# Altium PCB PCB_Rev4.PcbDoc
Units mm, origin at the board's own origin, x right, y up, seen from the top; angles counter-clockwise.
Board outline 44.96 x 25.15 mm, 4 copper layers (Top Layer, Layer 1 (GND), Layer 2 (PWR), Bottom Layer), stack 1.716 mm thick; 62 components, 47 nets, 255 pads, 96 vias.
Unrouted connection lines stored in the file: 55.
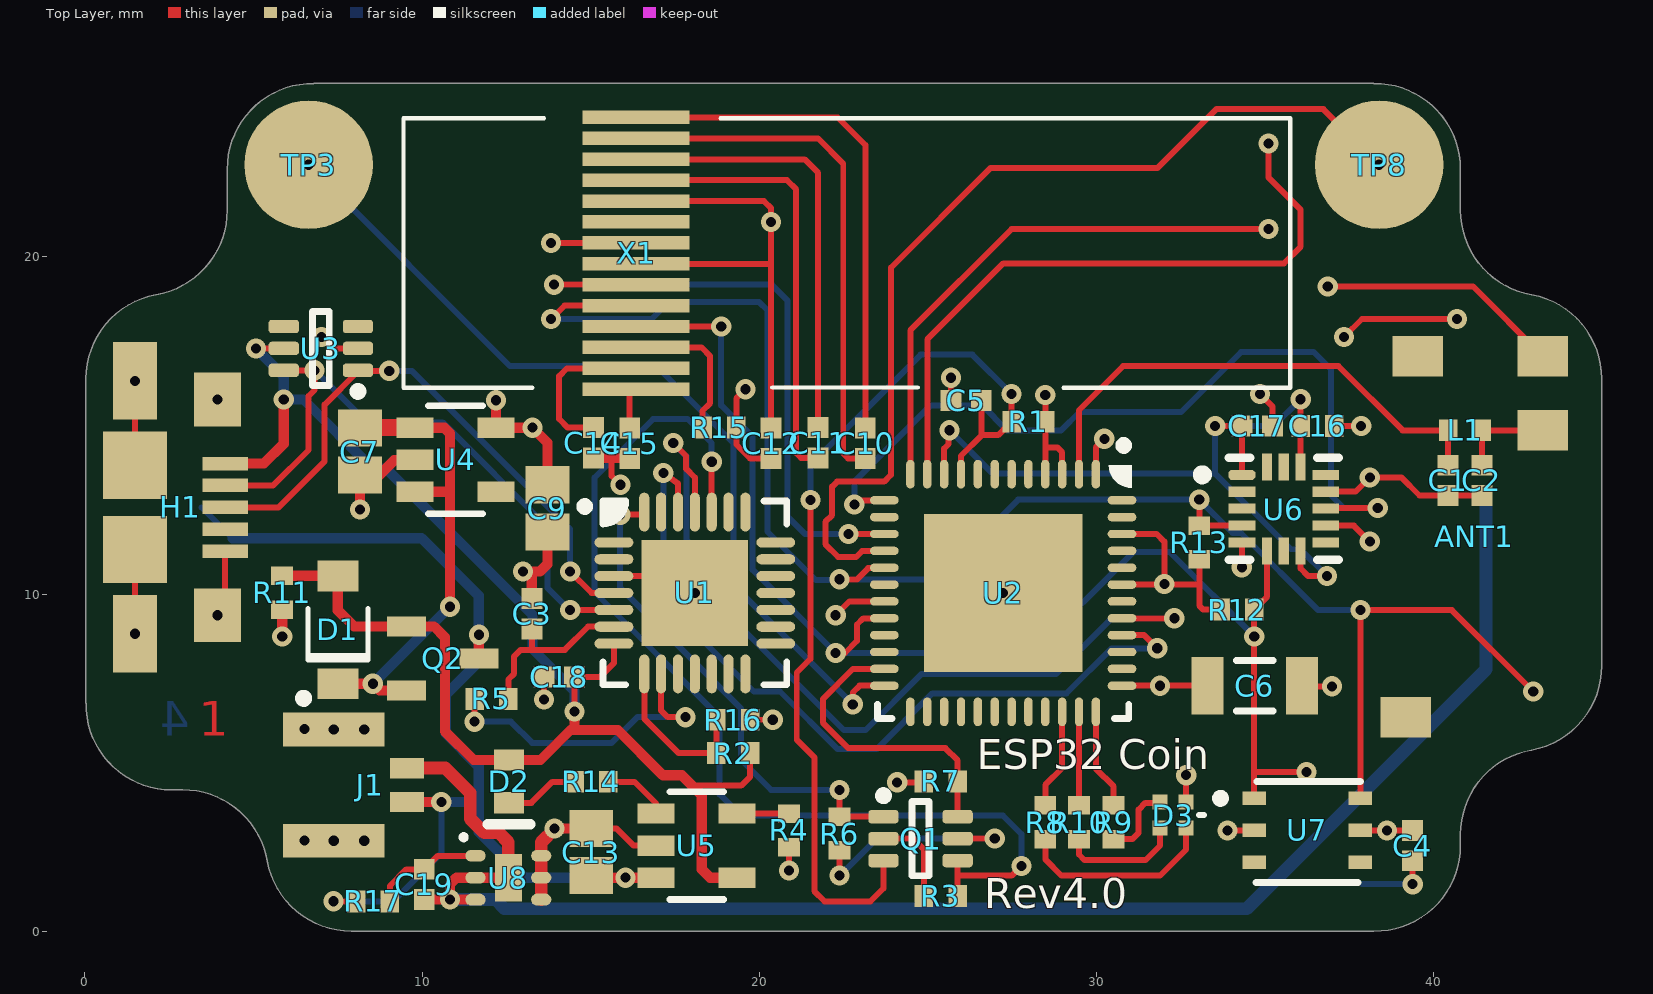
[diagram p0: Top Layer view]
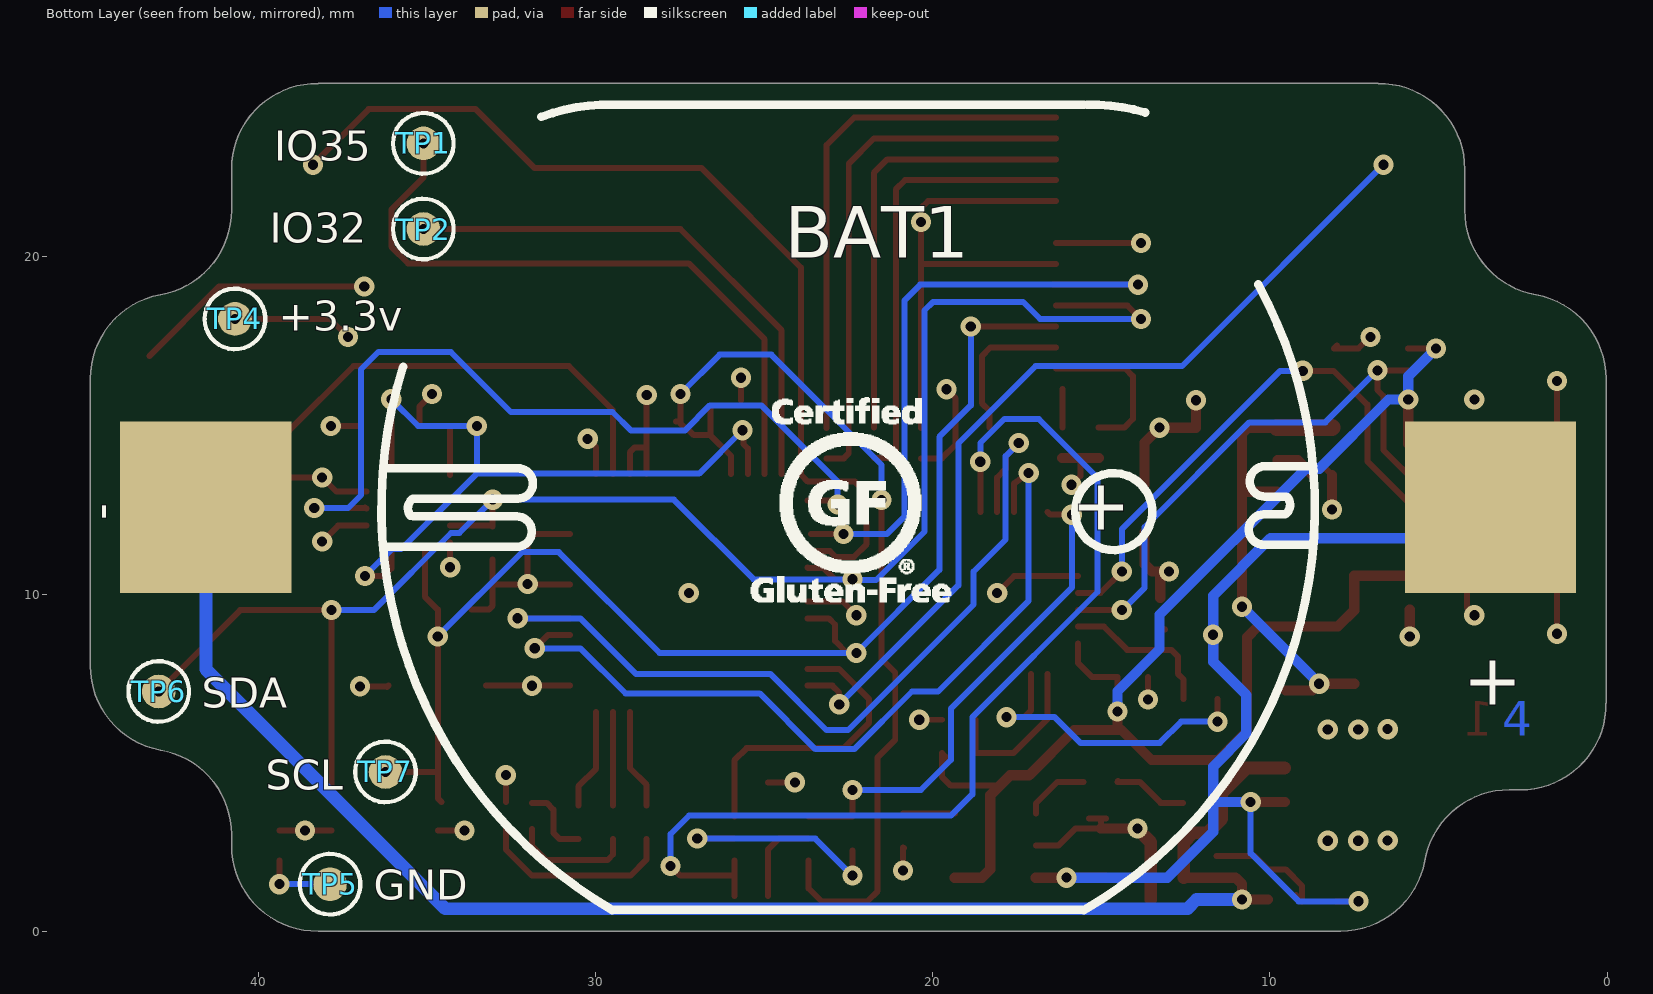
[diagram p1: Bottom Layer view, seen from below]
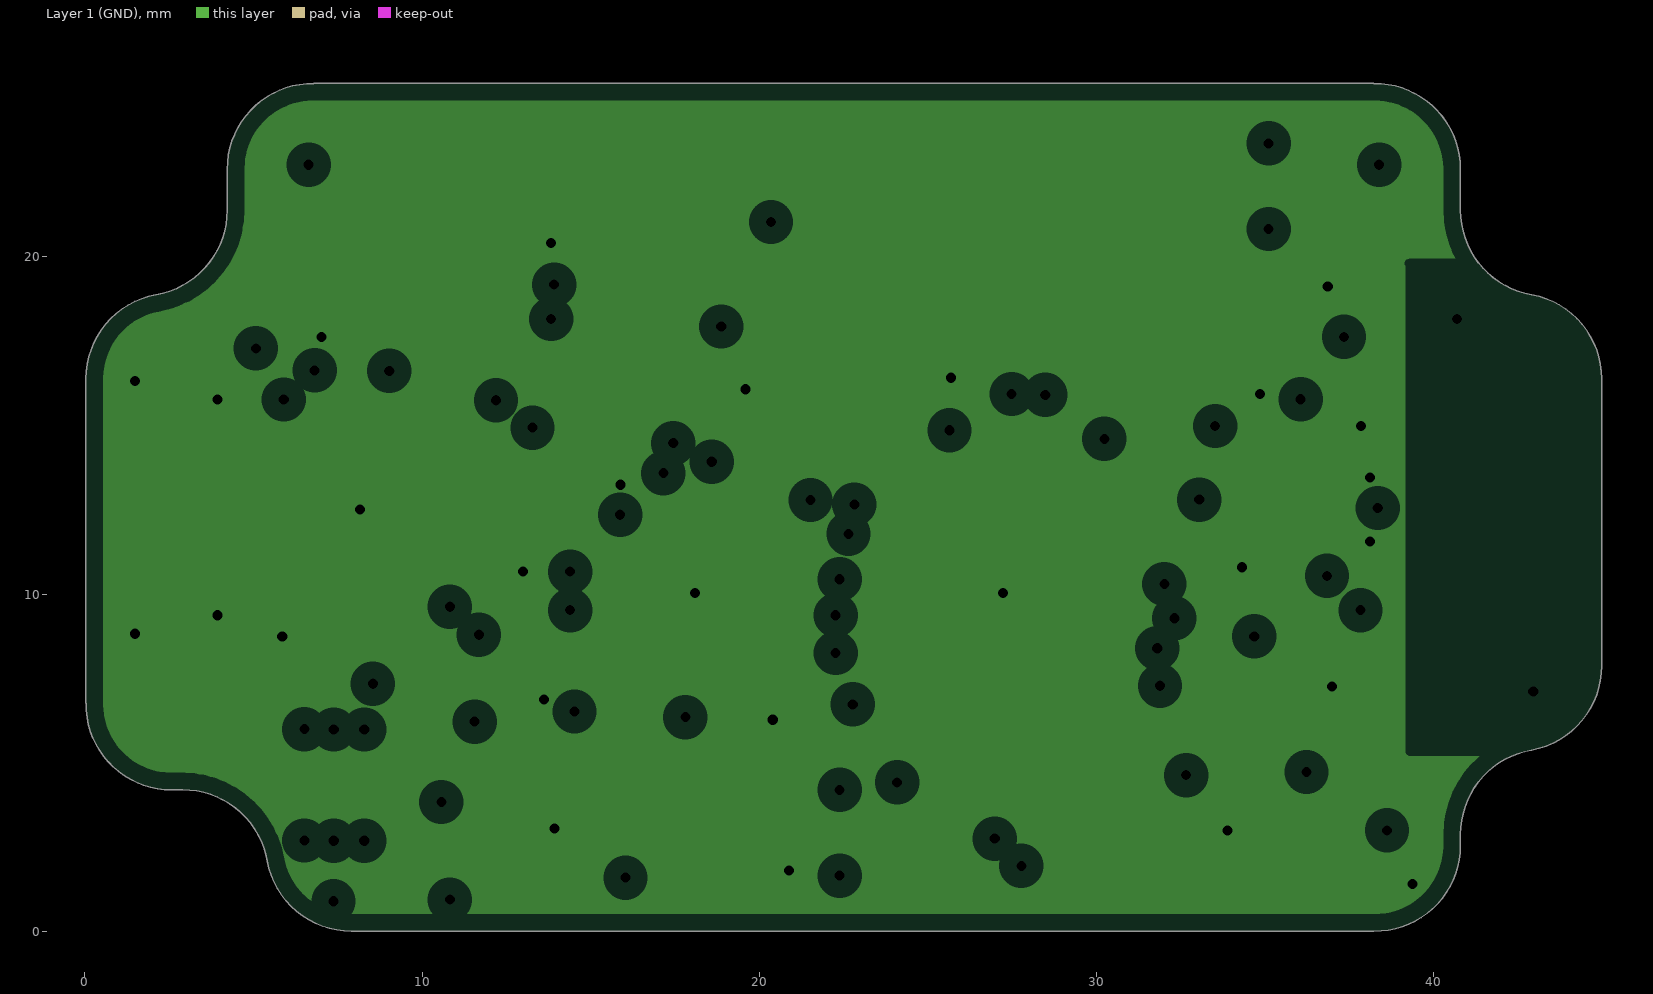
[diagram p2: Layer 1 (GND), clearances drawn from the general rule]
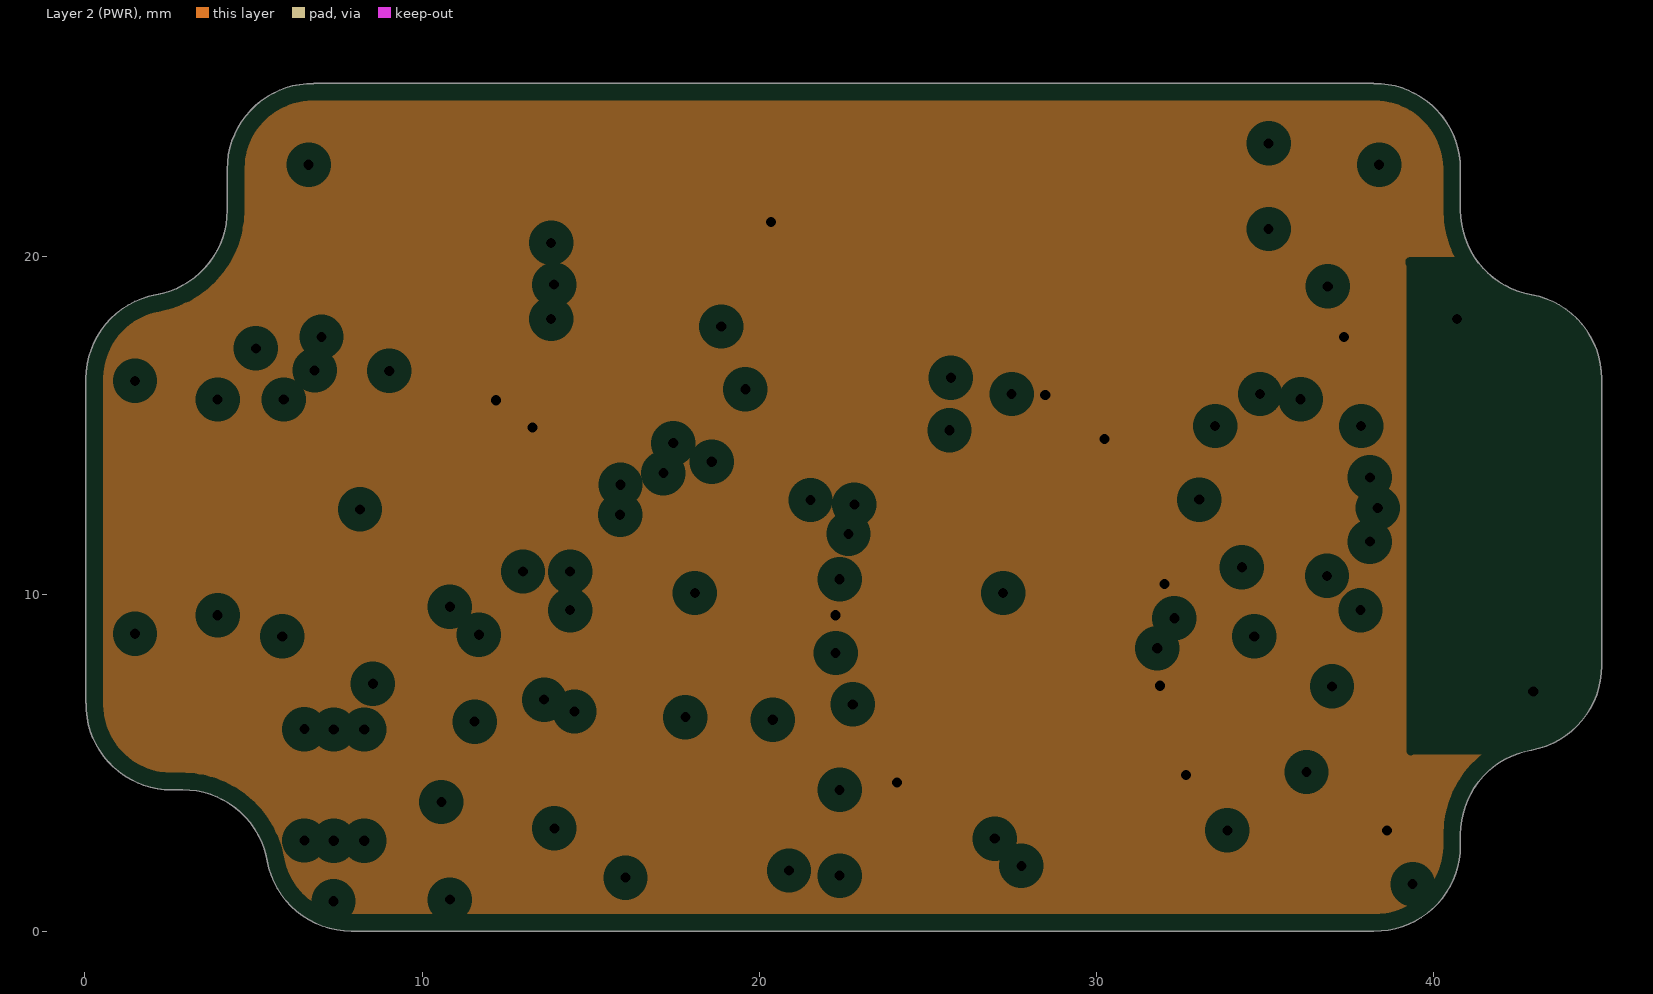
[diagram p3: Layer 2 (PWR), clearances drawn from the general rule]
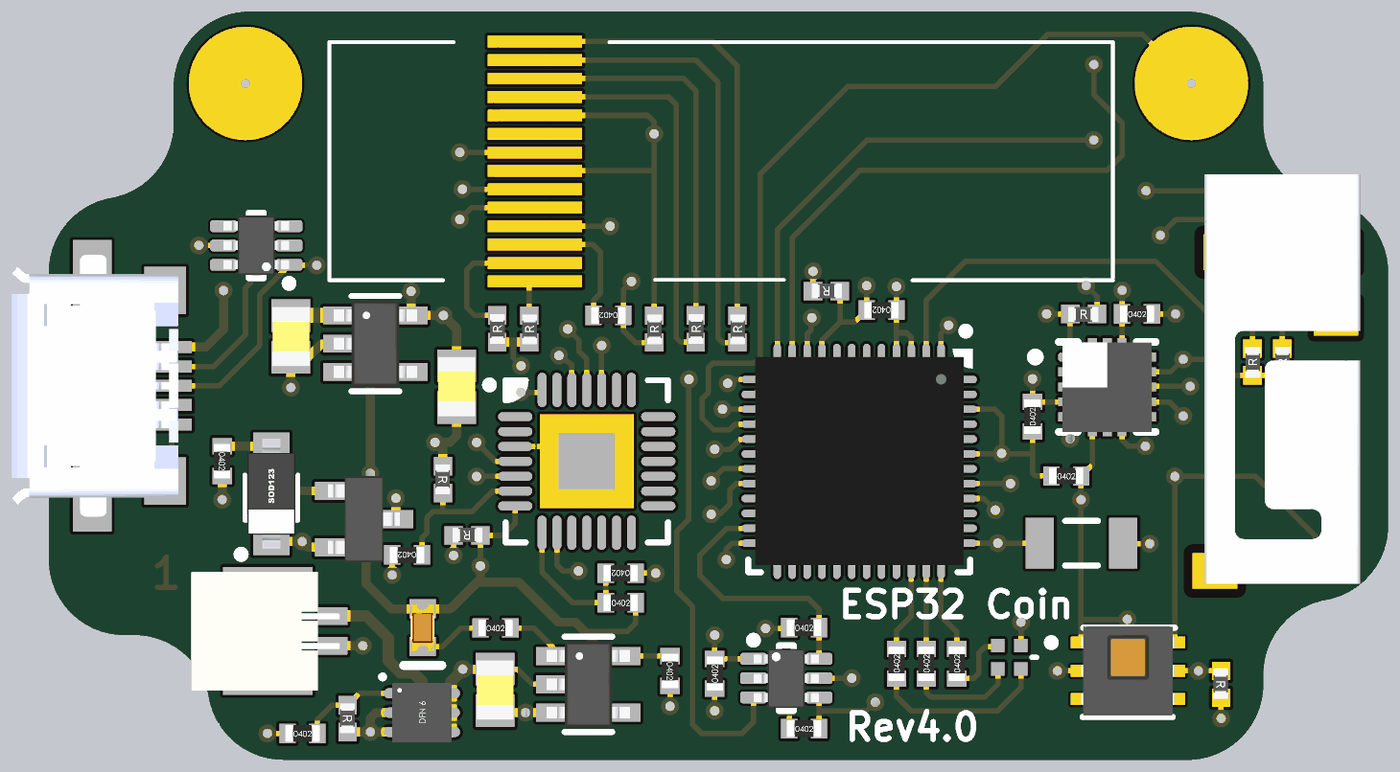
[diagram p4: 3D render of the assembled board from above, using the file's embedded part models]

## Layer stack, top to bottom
Top Solder: solder mask 0.0102, Solder Resist, Dk 3.5
Top Layer: signal copper 0.0356
Dielectric 2: prepreg 0.0711, PP-006, Dk 4.1
Layer 1 (GND): plane copper 0.035, net GND
Dielectric 1: dielectric 1.4326, FR-4, Dk 4.8
Layer 2 (PWR): plane copper 0.035, net +3.3V
Dielectric 3: prepreg 0.0711, PP-006, Dk 4.1
Bottom Layer: signal copper 0.0356
Bottom Solder: solder mask 0.0102, Solder Resist, Dk 3.5

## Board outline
2.572,4.196 cw(c2.572,6.736) 0.032,6.761 0.03,6.761 0.03,16.383 cw(c2.57,16.383) 2.111,18.881 ccw(c1.681,21.385) 4.221,21.385 4.221,22.604 cw(c6.761,22.604) 6.786,25.144 6.786,25.146 38.231,25.146 38.231,25.144 cw(c38.256,22.604) 40.796,22.604 40.796,21.385 ccw(c43.336,21.385) 42.907,18.881 cw(c42.448,16.383) 44.988,16.383 44.988,7.874 cw(c42.448,7.874) 42.907,5.376 ccw(c43.336,2.872) 40.796,2.872 40.796,2.542 cw(c38.256,2.542) 38.231,0.002 38.231,0 7.903,0 7.903,0.005 cw(c7.903,2.545) 5.405,2.086 ccw(c2.902,1.656) 2.902,4.196

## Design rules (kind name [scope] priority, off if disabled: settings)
Clearance Clearance_H1 [All vs InComponent('H1')] p1: gap=0.241 ignorepadtopadclearanceinfootprint=FALSE
Clearance Clearance_U3 [All vs InComponent('U3')] p2: gap=0.241 ignorepadtopadclearanceinfootprint=FALSE
Clearance Clearance_Q1 [All vs InComponent('Q1')] p3: gap=0.241 ignorepadtopadclearanceinfootprint=FALSE
Clearance Clearance_X1 [All vs InComponent('X1')] p4: gap=0.216 ignorepadtopadclearanceinfootprint=FALSE
Clearance Clearance_U2 [All vs InComponent('U2')] p5: gap=0.241 ignorepadtopadclearanceinfootprint=FALSE
Clearance Clearance_U1 [All vs InComponent('U1')] p6: gap=0.198 ignorepadtopadclearanceinfootprint=FALSE
Clearance Clearance_U6 [All vs InComponent('U6')] p7: gap=0.191 ignorepadtopadclearanceinfootprint=FALSE
Clearance [All] p8: gap=0.254 ignorepadtopadclearanceinfootprint=FALSE except(0: Arc-Hole Track-Hole SMDPad-Hole THPad-Hole Via-Hole Fill-Hole Poly-Hole Region-Hole Text-Hole)
MinimumSolderMaskSliver MinimumSolderMaskSliver_X1 [All vs InComponent('X1')] p1: minsoldermaskwidth=0.015
MinimumSolderMaskSliver [All] p2: minsoldermaskwidth=0.025
PlaneClearance [All] p1: clearance=0.508
PlaneConnect [All] p1: planeconnectstyle=Direct reliefexpansion=0.508 reliefentries=4 reliefconductorwidth=0.254 reliefairgap=0.254
PolygonConnect [All] p1: connectstyle=Relief reliefconductorwidth=0.254 reliefentries=4 polygonreliefangle="90 Angle" airgapwidth=0.254
RoutingVias [All] p1: holewidth=0.3 width=0.6 viastyle="Through Hole" minholewidth=0.3 minwidth=0.6 maxholewidth=0.3 maxwidth=0.6
SilkToSilkClearance [All] p1: silktosilkclearance=0.127
SilkToSolderMaskClearance [IsPad] p1: minsilkscreentomaskgap=0.127 clearancetoexposedcopper=TRUE
SolderMaskExpansion [All] p1: expansion=0.102
Width [All] p1: maxlimit=1.016 minlimit=0.178 preferedwidth=0.178
25 further rules are at their usual default settings.

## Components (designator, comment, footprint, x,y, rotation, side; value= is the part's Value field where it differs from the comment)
ANT1 "RF ANT 2.4GHZ STAMPED MET SLD" PRO-OB-440 43.235,17.059 r0 top locked
BAT1 "BATTERY-HOLDER (2450)" BU2450SM-JJ-GTR 22.509,12.573 r0 bottom locked value="Coin Cell Holder"
C1 "=Value" CAPC1005X56N#1 40.432,13.373 r90 top
C2 "=Value" CAPC1005X56N#1 41.432,13.373 r90 top
C3 "4.7uF" CAPC1005X56N#2 13.263,9.42 r270 top
C4 "0.1uF" CAPC1005X56N#1 39.379,2.542 r270 top
C5 "0.1uF" CAPC1005X56N#2 26.133,15.748 r180 top
C6 "100uF" CAPC3216X160L 34.695,7.283 r0 top
C7 "10uF" CAPC2012X140N 8.158,14.228 r270 top
C9 "10uF" CAPC2012X140N 13.716,12.543 r270 top
C10 "1uF" CAPC1005X56N#2 23.144,14.478 r90 top
C11 "1uF" CAPC1005X56N#2 21.747,14.489 r90 top
C12 "1uF" CAPC1005X56N#2 20.35,14.478 r90 top
C13 "10uF" CAPC2012X140N 15.016,2.351 r90 top
C14 "4.7uF" CAPC1005X56N#2 15.079,14.489 r90 top
C15 "2.2uF" CAPC1005X56N#2 16.159,14.478 r90 top
C16 "0.1uF" RESC1005X40L 36.557,14.986 r0 top
C17 "0.1uF" CAPC1005X56N#2 34.767,14.986 r0 top
C18 "1uF" CAPC1005X56N#2 14.069,7.544 r180 top
C19 "0.1uF" CAPC1005X56N#2 10.063,1.39 r270 top
D1 "MBR0520-TP" SOD123 7.502,8.941 r90 top value=MBR0520
D2 "LED_0603" LED1608X55N-RED 12.582,4.445 r90 top value=Red
D3 "RGB" FC-B1010RGBT-HG 32.273,3.449 r0 top value="RGB Led"
H1 "Micro USB" 1981584-1 2.824,12.573 r270 top locked
J1 "CON2" JST_Micro_2PIN 9.555,4.336 r270 top locked
L1 "Inductor" RESC1005X40L 40.932,14.859 r180 top value=1.8nH
Q1 "BC847S" SOT65P210X110-6N 24.784,2.723 r0 top value=2NPN
Q2 "FDN340P" SOT95P240X110-3N 10.609,8.09 r0 top locked value="Mosfet P-H"
R1 "10K" RESC1005X40L 27.983,15.113 r180 top
R2 "22.1K" RESC1005X40L 19.227,5.283 r0 top
R3 "10K" RESC1005X40L 25.384,1.051 r0 top
R4 "43K" RESC1005X40L 20.883,2.99 r270 top
R5 "4.7K" RESC1005X40L 12.057,6.89 r180 top
R6 "10K" RESC1005X40L 22.382,2.898 r90 top
R7 "10K" RESC1005X40L 25.384,4.445 r0 top
R8 "1K" RESC1005X40L 28.483,3.233 r90 top
R9 "1K" RESC1005X40L 30.51,3.233 r90 top
R10 "1K" RESC1005X40L 29.483,3.233 r90 top
R11 "100K" RESC1005X40L 5.851,10.041 r270 top
R12 "4.7K" RESC1005X40L 34.18,9.541 r0 top
R13 "4.7K" RESC1005X40L 33.05,11.533 r90 top
R14 "2K" RESC1005X40L 15.024,4.434 r0 top
R15 "390K" RESC1005X40L 18.818,14.939 r180 top
R16 "47.5K" RESC1005X40L 19.227,6.274 r180 top
R17 "100R" RESC1005X40L 8.547,0.889 r0 top
TP1 "Test Point, 1mm Top Layer" TP100TL#1 35.107,23.368 r90 bottom
TP2 "Test Point, 1mm Top Layer" TP100TL#1 35.107,20.828 r90 bottom
TP3 "Test Point, 1mm Top Layer" TP100TL#2 11.485,24.765 r90 top
TP4 "Test Point, 1mm Top Layer" TP100TL#1 40.695,18.161 r90 bottom
TP5 "Test Point, 1mm Top Layer" TP100TL#1 37.876,1.397 r90 bottom
TP6 "Test Point, 1mm Top Layer" TP100TL#1 42.956,7.112 r90 bottom
TP7 "Test Point, 1mm Top Layer" TP100TL#1 36.231,4.725 r90 bottom
TP8 "Test Point, 1mm Top Layer" TP100TL#3 38.384,22.733 r90 top
U1 "CP2102N" 28-QFN 18.089,10.033 r0 top locked
U2 "ESP32-PICO-D4" QFN48 27.233,10.033 r270 top
U3 "PESD5V0L5UY" SOT65P210X110-6N 6.997,17.312 r180 top value=ESD
U4 "HT7833" SOT95P280X144-5N 10.992,13.986 r0 top value="LDO 3.3V"
U5 "SL4054ST25P" SOT95P280X144-5N 18.143,2.54 r0 top
U6 "ACCEL" QFN3X3_16_1.2 35.556,12.522 r0 top value=LIS3DHTR
U7 "HDC1080DMBT" HDC1080 36.255,2.992 r0 top value=Humidity/Temperature
U8 "XB6566H0" "DFN-6 2x2mm" 12.557,1.59 r0 top value="Battery Protection"
X1 "OLED_GLASS 96x16" "OLED_GLASS 96x16" 9.449,16.117 r180 top locked

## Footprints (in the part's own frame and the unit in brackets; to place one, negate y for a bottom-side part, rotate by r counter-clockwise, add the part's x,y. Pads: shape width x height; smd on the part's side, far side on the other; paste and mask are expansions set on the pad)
28-QFN [mm] "QFN, 28-Leads, Body 5.00x5.00mm, Pitch 0.50mm, Thermal Pad 3.15x3.15mm, IPC Medium Density"
  oval 1.15x0.3 smd: 1(-2.4,1.5) 2(-2.4,1) 3(-2.4,0.5) 4(-2.4,0) 5(-2.4,-0.5) 6(-2.4,-1) 7(-2.4,-1.5) 15(2.4,-1.5) 16(2.4,-1) 17(2.4,-0.5) 18(2.4,0) 19(2.4,0.5) 20(2.4,1) 21(2.4,1.5)
  oval 0.3x1.15 smd: 8(-1.5,-2.4) 9(-1,-2.4) 10(-0.5,-2.4) 11(0,-2.4) 12(0.5,-2.4) 13(1,-2.4) 14(1.5,-2.4) 22(1.5,2.4) 23(1,2.4) 24(0.5,2.4) 25(0,2.4) 26(-0.5,2.4) 27(-1,2.4) 28(-1.5,2.4)
  rect 3.15x3.15 smd paste-0.635: 29(0,0)
  silkscreen extent -3.39,-2.73 2.73,2.73, body extent -2.58,-2.57 2.57,2.58, height 1
1981584-1 [mm] "CONN RCPT MICRO USB TYPE AB"
  rect 0.4x1.35 smd: 1(-1.3,1.338) 2(-0.65,1.338) 3(0,1.338) 4(0.65,1.338) 5(1.3,1.338)
  rect 2.3x1.3 smd: 6(-3.75,-1.337) 6(3.75,-1.337)
  rect 1.6x1.4 smd: 6(-3.2,1.113) 6(3.2,1.113)
  rect 2x1.9 smd: 6(-1.25,-1.337) 6(1.25,-1.337)
  body extent -4.4,-4.05 4.4,1.55, height 2.75
BU2450SM-JJ-GTR [mm] "HOLDER,BATT,COIN,24.5MM,SMT"
  rect 5.08x5.08 smd: 1(-19.05,0) 2(19.05,0)
  silkscreen extent -13.84,-11.94 13.84,11.95, body extent -21.38,-14.48 88.52,12.32, height 7.38
CAPC1005X56N#1 [mm] "Chip Capacitor, 2-Leads, Body 1.0x0.5mm, IPC Medium Density (0402 ceramic)"
  rect 0.62x0.62 smd paste-0.305: 1(-0.45,0) 2(0.45,0)
  body extent -0.55,-0.3 0.55,0.3, height 0.6
CAPC1005X56N#2 [mm] "Chip Capacitor, 2-Leads, Body 1.0x0.5mm, IPC Medium Density (0402 ceramic)"
  rect 0.62x0.62 smd: 1(-0.45,0) 2(0.45,0)
  body extent -0.55,-0.3 0.55,0.3, height 0.6
CAPC2012X140N [mm] "Chip Capacitor, 2-Leads, Body 2.0x1.3mm, IPC Medium Density (0805 ceramic)"
  rect 1.1x1.3 smd: 1(-0.7,0) 2(0.7,0)
  body extent -1,-0.62 1,0.63, height 1.24
CAPC3216X160L [mm] "Chip Capacitor, 2-Leads, Body 3.2x1.6mm, IPC Least Density(C1206)"
  rect 0.95x1.7 smd: 1(-1.4,0) 2(1.4,0)
  silkscreen extent -0.55,-0.75 0.55,0.75, body extent -1.7,-0.9 1.7,0.9, height 1.9
"DFN-6 2x2mm" [mm] "DFN, 6-Leads, Body 2.00x2.00mm, Pitch 0.65mm, IPC High Density"
  oval 0.6x0.35 smd: 1(-0.975,0.65) 2(-0.975,0) 3(-0.975,-0.65) 4(0.975,-0.65) 5(0.975,0) 6(0.975,0.65)
  rect 0.8x1.4 smd paste-0.15: 7(0,0)
  silkscreen extent -1.37,1.15 -1.27,1.25, body extent -1,-1 2.65,1, height 4.99
FC-B1010RGBT-HG [mm] "LED,RGB,SMD,RoHS"
  rect 0.45x0.45 smd: 1(0.387,0.388) 2(0.387,-0.387) 3(-0.387,-0.387) 4(-0.387,0.388)
  silkscreen extent 0.76,0 0.91,0, body extent -0.53,-0.55 0.53,0.58, height 1.2
HDC1080 [mm] "Temp/Humidity Sensor"
  rect 0.7x0.4 smd paste-0.381 mask+0.076: 1(-1.575,0.95) 2(-1.575,0) 3(-1.575,-0.95) 4(1.575,-0.95) 5(1.575,0) 6(1.575,0.95)
  silkscreen extent -2.7,-1.55 1.57,1.45, body extent -1.55,-1.5 1.55,1.5, height 0.85
JST_Micro_2PIN [mm]
  rect 0.6x1 smd: 1(0.5,0) 2(-0.5,0)
  rect 1x3 smd: ""(-1.65,-2.175) ""(1.65,-2.175)
  body extent -1.99,-4.74 2,0.24, height 2.9
LED1608X55N-RED [mil] "Chip LED RED, 2-Leads, Body 1.6x0.8mm, IPC Medium Density (0603 med)"
  rect 25x35 smd: 1(-25,0) 2(25,0)
  silkscreen extent -50,-25 -50,25, body extent -31,-16 31,16, height 24
"OLED_GLASS 96x16" [mm] "OLED_GLASS 96x16"
  rect 3.175x0.4 smd paste-2.54: 1(-6.9,-8.02) 2(-6.9,-7.4) 3(-6.9,-6.78) 4(-6.9,-6.16) 5(-6.9,-5.54) 6(-6.9,-4.92) 7(-6.9,-4.3) 8(-6.9,-3.68) 9(-6.9,-3.06) 10(-6.9,-2.44) 11(-6.9,-1.82) 12(-6.9,-1.2) 13(-6.9,-0.58) 14(-6.9,0.04)
  silkscreen extent -26.3,-8 0,0, body extent -26.3,-8 0,0, height 2
PRO-OB-440 [mm] "RF ANT 2.4GHZ STAMPED MET SLD"
  rect 1.5x1.2 smd paste-0.762 mask+0.2: 1(0,0) 2(0,-2.2)
  rect 1.5x1.2 smd paste-0.762 mask+0.3: 3(-3.7,0) 4(-4.064,-10.709)
  body extent -4.42,-11.14 7.98,2.61, height 3.56
QFN3X3_16_1.2 [mm] "QFN3X3_16_1.2"
  oct 0.8x0.3 smd: 1(-1.245,1.016)
  rect 0.8x0.3 smd: 2(-1.245,0.514) 3(-1.245,0.013) 4(-1.245,-0.489) 5(-1.245,-0.991) 9(1.245,-0.991) 10(1.245,-0.489) 11(1.245,0.013) 12(1.245,0.514) 13(1.245,1.016)
  rect 0.3x0.8 smd: 6(-0.495,-1.245) 7(0,-1.245) 8(0.495,-1.245) 14(0.495,1.245) 15(0,1.245) 16(-0.495,1.245)
  silkscreen extent -2.54,-1.5 1.63,1.52, body extent -1.51,-1.5 1.51,1.5, height 0.81
QFN48 [mm] "QFN, 48-Leads, Body 7x7mm, Pitch 0.5mm, IPC Medium Density"
  oval 0.85x0.25 smd: 1(-3.525,2.75) 2(-3.525,2.25) 3(-3.525,1.75) 4(-3.525,1.25) 5(-3.525,0.75) 6(-3.525,0.25) 7(-3.525,-0.25) 8(-3.525,-0.75) 9(-3.525,-1.25) 10(-3.525,-1.75) 11(-3.525,-2.25) 12(-3.525,-2.75) 25(3.525,-2.75) 26(3.525,-2.25) 27(3.525,-1.75) 28(3.525,-1.25) 29(3.525,-0.75) 30(3.525,-0.25) 31(3.525,0.25) 32(3.525,0.75) 33(3.525,1.25) 34(3.525,1.75) 35(3.525,2.25) 36(3.525,2.75)
  oval 0.25x0.85 smd: 13(-2.75,-3.525) 14(-2.25,-3.525) 15(-1.75,-3.525) 16(-1.25,-3.525) 17(-0.75,-3.525) 18(-0.25,-3.525) 19(0.25,-3.525) 20(0.75,-3.525) 21(1.25,-3.525) 22(1.75,-3.525) 23(2.25,-3.525) 24(2.75,-3.525) 37(2.75,3.525) 38(2.25,3.525) 39(1.75,3.525) 40(1.25,3.525) 41(0.75,3.525) 42(0.25,3.525) 43(-0.25,3.525) 44(-0.75,3.525) 45(-1.25,3.525) 46(-1.75,3.525) 47(-2.25,3.525) 48(-2.75,3.525)
  rect 4.7x4.7 smd paste-0.5: 49(0,0)
  silkscreen extent -4.5,-3.72 3.72,3.81, body extent -3.52,-3.51 3.5,3.51, height 0.78
RESC1005X40L [mm] "Chip Resistor, 2-Leads, Body 1.0x0.5mm, IPC Medium Density (0402)"
  rect 0.55x0.65 smd: 1(-0.5,0) 2(0.5,0)
  body extent -0.57,-0.27 0.58,0.28, height 0.41
SOD123 [mil] "Molded Diode, 2-Leads, Body 2.85x1.8mm, IPC Medium Density (SOD123)"
  rect 36x48 smd: 1(-63,0) 2(63,0)
  silkscreen extent -85,-35 25,45, body extent -73,-31 73,31, height 50
SOT65P210X110-6N [mm] "SC70, 6-Leads, Body 2.4x2.2mm (max), Pitch 0.65mm, IPC Medium Density"
  rrect50% 0.9x0.4 smd mask+0.076: 1(-1.1,0.675) 2(-1.1,0.025) 3(-1.1,-0.625) 4(1.1,-0.625) 5(1.1,0.025) 6(1.1,0.675)
  silkscreen extent -1.22,-1.07 0.25,1.42, body extent -1.1,-0.97 1.1,1.01, height 0.99
SOT95P240X110-3N [mm] "SOT23, 3-Leads, Body 3.0x2.5mm (max), Pitch 0.95mm, IPC Medium Density"
  rect 1.15x0.6 smd: 1(-1.075,0.95) 2(-1.075,-0.95) 3(1.075,0)
  body extent -1.2,-1.45 1.2,1.45, height 0.99
SOT95P280X144-5N [mm] "SOT23, 5-Leads, Body 3.1x3.0mm (max), Pitch 0.95mm, IPC Medium Density (RFMD SOT23-5)"
  rect 1.1x0.6 smd: 1(-1.2,0.95) 2(-1.2,0) 3(-1.2,-0.95) 4(1.2,-0.95) 5(1.2,0.95)
  silkscreen extent -0.8,-1.6 0.8,1.6, body extent -1.4,-1.45 1.4,1.45, height 1.45
TP100TL#1 [mm] "Test Point"
  round 1 smd paste-0.5 mask+0.076: 1(0,0)
  silkscreen extent -0.9,-0.9 0.9,0.9
TP100TL#2 [mm] "Test Point"
  round 3.81 smd paste-2.032 mask+0.076: 1(-2.032,4.851)
TP100TL#3 [mm] "Test Point"
  round 3.81 smd paste-2.032 mask+0.076: 1(0,0)

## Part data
ANT1: library part PRO-OB-440, Manufacturer="Proant AB"
BAT1: library part BU2450SM-JJ-GTR, "HOLDER,BATT,COIN,24.5MM,SMT", Manufacturer=MPD
C1 C2: library part CAP_0402, "DNP"
C3 C14: library part CAP_0603, "CAP CER 4.7uF 16V 0402", Manufacturer=Kyocera, PartNumber=CM05X5R475M16AH
C4 C5 C16 C17 C19: library part CAP_0402, "CAP CER 0.1uF 16V 0402", Manufacturer=CCTC, PartNumber=TCC0402X5R104M160AT
C6: library part CAP_1206, "CAP CER 100uF 6.3V 1206", Manufacturer="Taiyo Yuden", PartNumber=JMK316BJ107ML-T
C7 C9: library part CAP_0805, "CAP 10uF 0805", Manufacturer=Murata, PartNumber=GRM21BB31C106KE15L
C10 C11 C12 C18: library part CAP_0603, "CAP CER 1uF 16V 0402", Manufacturer=Murata, PartNumber=GRM155R61C105KA12D
C13: library part CAP_0805, "CAP CER 10uF 16V 0805", Manufacturer=Samsung, PartNumber=CL21A106KOQNNNG
C15: library part CAP_0402, "CAP CER 2.2uF 16V 0402", Manufacturer=Samsung, PartNumber=CL05A225KO5NQNC
D1: "DIODE SCHOTTKY 20V 500MA SOD123", Manufacturer=CJ, PartNumber=MBR0520
D2: "LED RED CLEAR 0603 SMD", Manufacturer=FNO, PartNumber=FC-DA1608HRK-620D
D3: library part FC-B1010RGBT-HG, "LED,RGB LED,SMD,RoHS", Manufacturer=Foshan
H1: library part 1981584-1, "CONN RCPT MICRO USB TYPE AB", Manufacturer="REG CON", PartNumber=C21377
J1: library part JST_Micro_CONN_2PIN, "JST MIcro CONN 2POS"
L1: "Inductor 1.8nH 0402", Manufacturer=GFBE, PartNumber=BKW0603UC1N8KGT
Q1: "TRANS 2NPN 44V 0.1A SC-70-6", Manufacturer=Changjiang
Q2: "MOSFET P-CH 20V 2A SOT-23", Manufacturer="On Semi"
R1 R3 R6 R7: library part RES_0402, "RES SMD 10K OHM 0402", Manufacturer=Guangdong, PartNumber=RC-02W1002FT
R2: library part RES_0603, "RES SMD 22.1K OHM 0402", Manufacturer=Yageo, PartNumber=RC0402FR-0722K1L
R4: library part RES_0603, "RES SMD 43K OHM 0402", Manufacturer=Uniroyal, PartNumber=0402WGF4302TCE
R5 R12 R13: library part RES_0603, "RES SMD 4.7K OHM 0402", Manufacturer=Yageo, PartNumber=RC0402FR-074K7L
R8 R9 R10: library part RES_0402, "RES SMD 1K OHM 0402", Manufacturer=Yageo, PartNumber=RC0402FR-071KL
R11: library part RES_0603, "RES SMD 100K OHM 0402", Manufacturer="Uniroyal Elec", PartNumber=0402WGF1003TCE
R14: library part RES_0603, "RES SMD 2K OHM 1% 1/10W 0402", Manufacturer="LIZ Elec", PartNumber=CR0402FF2001G
R15: library part RES_0603, "RES SMD 390K OHM 0402", Manufacturer=Guangdong, PartNumber=RC-02W3903FT
R16: library part RES_0603, "RES SMD 47.5K OHM 0402", Manufacturer=Yageo, PartNumber=RC0402FR-0747K5L
R17: library part RES_0603, "RES SMD 100R OHM 1% 1/10W 0402", Manufacturer=Yageo, PartNumber=RC0402FR-07100RL
TP1 TP2 TP3 TP4 TP5 TP6 TP7 TP8: Manufacturer=N/A
U1: "IC BRIDGE USB TO UART 28QFN", Manufacturer="Silicon Labs", PartNumber=CP2102N-A01-GQFN28
U2: "RF Transceiver ICs QFN-48_7x7x05P RoHS", Manufacturer=Espressif
U3: "TVS SOT-363 RoHS", Manufacturer=Yenji
U4: "IC LDO 3.3V 0.5A SOT23-5", Manufacturer=Holtek
U5: "Charger IC Lithium-Ion/Polymer SOT23-5", Manufacturer=Techfuse
U6: library part E-05-177, "IC ACCEL 2-16G I2C/SPI 16LGA", Manufacturer=STMicro, PartNumber=LIS3DHTR
U7: "Humidity/Temperature Sensor", Manufacturer="Texas Instruments"
U8: "IC Battery Protection", Manufacturer=XySemi
X1: "96x16 OLED_GLASS", Manufacturer=N/A, PartNumber=ER-OLED0.69-1W

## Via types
v1: diameter 0.6, hole 0.3, Top Layer to Bottom Layer, tented both sides, 96 vias

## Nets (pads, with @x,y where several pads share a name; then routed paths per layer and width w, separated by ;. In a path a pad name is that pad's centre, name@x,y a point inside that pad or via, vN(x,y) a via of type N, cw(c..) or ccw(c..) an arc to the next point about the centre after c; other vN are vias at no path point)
+3.3V: C4.1 C6.1 C9.1 C12.2 D3.1 R1.1 R7.1 R12.1 R13.1 TP4.1 U2.1 U2.3 U2.4 U2.19 U2.37 U2.43 U2.46 U4.5 U7.5 X1.5 X1.8 | length 40.9
  Top Layer w0.178: X1.8 20.307,19.797 20.35,19.754 ; X1.5 20.141,21.657 20.35,21.448 v1(20.35,21.037) C12.2 ; v1(22.265,9.373) 22.675,9.783 U2.19 ; v1(24.09,4.417) R7.1@24.885,4.417 ; U2.4 28.483,14.351 ; v1(28.483,15.908) R1.1 28.483,14.351 ; U2.3 28.983,14.206 28.838,14.351 28.483,14.351 ; U2.1 29.983,14.353 v1(30.235,14.605) ; U2.37 C6.1@33.245,7.283 ; U2.43 33.05,10.283 ; U2.46 31.787,11.783 32.013,11.557 v1(32.013,10.3) ; D3.1 v1(32.661,4.631) ; R13.1 33.05,9.657 33.165,9.541 R12.1 ; v1(37.342,17.628) 37.876,18.161 v1(40.695,18.161) ; U7.5 v1(38.617,2.992) C4.1
  Top Layer w0.305: v1(12.192,15.748) U4.5 v1(13.276,14.936) 13.716,14.496 C9.1
  other v1: 31.886,7.283
ACCEL_PWR: C16.1 C17.1 U2.10 U6.1 U6.8 U6.14 | length 24.3
  Top Layer w0.178: U2.10 25.483,14.318 25.618,14.453 25.618,14.834 v1(25.643,14.859) ; v1(33.522,14.986) C17.1 34.312,14.981 U6.1 ; U6.8 36.052,10.761 36.272,10.541 v1(36.839,10.541) ; U6.14 36.052,14.981 C16.1 v1(36.057,15.781)
  Bottom Layer w0.178: v1(25.643,14.859) 26.929,13.573 33.528,13.573 ; v1(36.057,15.781) 35.262,14.986 v1(33.522,14.986) 33.522,13.579 33.528,13.573 ; v1(36.839,10.541) 36.049,11.331 35.771,11.331 33.528,13.573
BLUE: R9.2 U2.36 | length 3
  Top Layer w0.178: U2.36 29.983,4.824 30.51,4.297 R9.2
D+: H1.3 U1.4 U3.1 | length 17.8
  Top Layer w0.178: H1.3 5.745,12.573 7.112,13.94 7.112,15.622 8.112,16.622 v1(9.026,16.622) ; v1@14.391,10.546 v1(14.391,10.668) 15.026,10.033 U1.4
  Bottom Layer w0.178: v1(9.026,16.622) 9.694,16.622 14.391,11.925 v1(14.391,10.668)
D-: H1.2 U1.5 U3.6 | length 19.2
  Top Layer w0.178: H1.2 5.582,13.223 6.634,14.275 6.634,15.875 6.811,16.052 v1(6.811,16.637) U3.6 ; v1(14.391,9.525) 15.681,9.525 U1.5
  Bottom Layer w0.178: v1(6.811,16.637) 8.354,15.094 10.611,15.094 13.716,11.989 13.716,10.185 v1@14.36,9.541 ; v1@14.36,9.607 v1@14.36,9.541 ; v1(14.391,9.525) v1@14.376,9.525 ; v1@14.36,9.541 14.36,9.525 v1@14.376,9.525 ; v1@14.36,9.541 v1@14.376,9.525
DTR: Q1.1 R6.2 U1.28 | length 14.9
  Top Layer w0.178: v1(15.875,12.354) 16.51,12.354 U1.28 ; v1(22.382,4.193) R6.2 Q1.1
  Bottom Layer w0.178: v1(15.875,12.354) 15.875,10.19 19.461,6.604 19.461,5.08 20.348,4.193 v1(22.382,4.193)
EN: C5.1 Q1.3 R1.2 U2.9 | length 28.2
  Top Layer w0.178: v1(21.518,12.791) 21.518,8.08 21.112,7.674 21.112,5.678 21.634,5.156 21.634,1.191 21.936,0.889 23.299,0.889 23.684,1.274 Q1.3 ; U2.9 25.983,14.102 26.594,14.713 ; C5.1@26.594,15.494 26.594,14.713 ; R1.2@27.483,15.141 v1(27.483,15.936) ; R1.2@27.61,15.113 R1.2 27.483,15.063 27.297,14.877 27.247,14.877 27.083,14.713 26.594,14.713
  Bottom Layer w0.178: v1(21.518,12.791) 21.518,13.832 24.787,17.101 26.318,17.101 v1(27.483,15.936)
GND: ANT1.1 C1.1 C2.1 C3.1 C4.2 C5.2 C6.2 C7.2 C9.2 C12.1 C13.2 C14.1 C15.1 C16.2 C17.2 C18.2 H1.5 H1.6 R4.2 R11.2 R15.1 R16.1 TP5.1 U1.3 U1.29 U2.49 U3.2 U4.2 U5.2 U6.5 U6.10 U6.12 U7.2 U8.4 U8.5 U8.6 X1.7 | length 53.6
  Top Layer w0.178: v1(1.486,8.823) H1.6@1.486,11.323 ; H1.6@1.486,13.823 v1(1.486,16.323) ; v1(3.936,9.373) 4.161,9.598 H1.5 ; v1(7.015,17.628) 7.033,17.628 7.374,17.287 U3.2 U3.2@8.008,17.376 ; C7.2 C7.2@8.346,13.716 ; C7.2@8.666,13.538 C7.2@8.742,13.538 ; U4.2@9.776,13.97 U4.2 ; v1@12.996,10.668 v1(12.994,10.669) v1@13.058,10.733 ; C3.1@13.248,9.885 C3.1 ; v1(13.619,6.871) C18.2 ; v1(13.826,20.417) X1.7 ; v1@13.925,3.035 v1(13.925,3.051) ; C13.2@14.868,3.34 C13.2@15.359,3.34 ; C13.2@15.01,3.232 C13.2@15.016,3.226 ; C13.2 15.762,3.051 16.273,2.54 U5.2 ; 15.619,14.039 15.619,13.508 v1(15.884,13.243) v1@15.884,13.357 ; U1.3 17.589,10.533 v1(18.089,10.033) ; C15.1@16.129,13.998 C15.1 ; v1(19.589,16.077) 19.318,15.806 R15.1 19.318,14.437 19.727,14.028 C12.1 ; R16.1 v1(20.4,6.274) ; R4.2@20.858,2.465 R4.2 v1(20.883,1.803) ; C5.2 v1(25.683,16.416) ; v1(33.885,2.992) U7.2 ; v1(34.312,10.796) U6.5 ; v1(34.851,15.936) 35.217,15.57 C17.2 ; C6.2@36.145,7.283 36.189,7.239 36.215,7.265 v1(36.987,7.265) ; U6.10 37.633,12.033 v1(38.109,11.557) ; U6.12 37.683,13.036 v1(38.109,13.462) 39.044,13.462 39.583,12.923 C2.1 ; v1(36.86,19.126) 41.168,19.126 ANT1.1 ; C16.2 v1(37.852,14.986) ; v1(39.379,1.397) C4.2
  Top Layer w0.305: v1(5.851,8.746) R11.2 ; v1(8.158,12.512) C7.2 ; C7.2@8.742,13.538 9.174,13.97 U4.2@9.776,13.97 ; v1@12.996,10.668 13.496,10.668 13.716,10.888 C9.2 ; C3.1@13.248,9.885 v1@13.248,10.668 ; v1(13.925,3.051) C13.2 ; C14.1 15.619,14.039 C15.1@16.159,14.039
  Top Layer w0.381: U8.4 U8.5 U8.6 13.532,2.642 v1@13.925,3.035
  Bottom Layer w0.178: TP5.1 v1(39.379,1.397)
  other v1: 27.233,10.033 3.936,15.773
GPIO32: TP2.1 U2.12 | length 16.1
  Top Layer w0.178: U2.12 24.483,17.824 27.487,20.828 v1(35.107,20.828)
GPIO35: TP1.1 U2.11 | length 19.7
  Top Layer w0.178: U2.11 24.983,17.554 27.241,19.812 35.564,19.812 36.057,20.305 36.057,21.403 35.107,22.353 v1(35.107,23.368)
GREEN: R10.2 U2.35 | length 2.8
  Top Layer w0.178: R10.2 U2.35
INT1: U2.13 U6.11 | length 25
  Top Layer w0.178: v1(22.819,12.656) 22.946,12.783 U2.13 ; U6.11 U6.11@36.82,12.554 ; U6.11@36.839,12.573 U6.11@36.82,12.554 ; v1(38.344,12.554) U6.11@36.82,12.554
  Bottom Layer w0.178: v1(22.819,12.656) 22.819,13.334 25.081,15.596 26.608,15.596 27.345,14.859 28.956,14.859 29.499,15.402 32.512,15.402 34.29,17.18 36.444,17.18 36.957,16.667 36.957,12.935 37.338,12.554 v1(38.344,12.554)
IO0: Q1.6 R7.2 U2.23 | length 9
  Top Layer w0.178: U2.23 22.781,7.783 21.884,6.886 21.884,6.186 22.637,5.433 25.52,5.433 25.884,5.069 R7.2 Q1.6
NetANT1_2: ANT1.2 C2.2 L1.1 | length 2.8
  Top Layer w0.178: C2.2 L1.1 ANT1.2
NetBAT1_2: BAT1.2 C19.2 J1.2 U8.2 U8.3 U8.7 | length 47.7
  Top Layer w0.178: J1.2 J1.2@9.563,4.844
  Top Layer w0.305: C19.2 v1(10.825,0.94) ; U8.3@11.455,0.94 v1(10.825,0.94) ; U8.7 U8.2 11.018,1.59 10.825,1.397 v1(10.825,0.94)
  Top Layer w0.381: J1.2@9.563,4.844 10.685,4.844 11.43,4.099 11.43,3.337 11.846,2.921 12.278,2.921 12.557,2.642 U8.7
  Bottom Layer w0.381: v1(10.825,0.94) 12.176,0.94 12.446,0.67 34.456,0.67 41.559,7.773 BAT1.2
NetC1_2: C1.2 L1.2 U2.2 | length 15.4
  Top Layer w0.178: U2.2 29.483,15.452 30.795,16.764 37.176,16.764 39.081,14.859 L1.2 ; C1.2 L1.2 ; L1.2@40.532,14.759 L1.2
NetC3_2: C3.2 R5.1 U1.6 | length 5.5
  Top Layer w0.178: R5.1 12.557,7.468 12.73,7.641 12.73,8.155 12.921,8.346 13.263,8.346 ; C3.2@13.111,8.945 13.136,8.97 13.155,8.951 C3.2@13.263,8.951 ; C3.2 C3.2@13.263,8.951 ; U1.6 14.922,9.033 14.235,8.346 13.263,8.346 ; 13.263,8.346 C3.2@13.263,8.951
NetC7_1: C7.1 D1.1 Q2.2 U4.1 U4.3 | length 14.4
  Top Layer w0.178: D1.1 D1.1@7.56,7.283 ; C7.1 C7.1@8.166,14.936
  Top Layer w0.305: D1.1 v1(8.539,7.341) 8.736,7.144 Q2.2@9.534,7.144 ; U4.3 10.825,13.036 ; U4.1 10.662,14.936 10.825,14.774 10.825,13.036 ; v1(10.825,9.626) 10.825,13.036
  Top Layer w0.508: C7.1@8.166,14.936 U4.1
  Bottom Layer w0.178: v1(8.539,7.341) v1@8.539,7.394
  Bottom Layer w0.305: v1(8.539,7.341) v1(10.825,9.626)
NetC10_1: C10.1 X1.2 | length 15.8
  Top Layer w0.178: X1.2 21.741,23.517 22.491,22.767 22.491,14.173 22.636,14.028 C10.1
NetC10_2: C10.2 X1.1 | length 15.5
  Top Layer w0.178: X1.1 22.328,24.137 23.144,23.321 C10.2
NetC11_1: C11.1 X1.4 | length 13.4
  Top Layer w0.178: X1.4 20.822,22.277 21.094,22.005 21.094,14.184 21.239,14.039 C11.1
NetC11_2: C11.2 X1.3 | length 13.1
  Top Layer w0.178: X1.3 21.345,22.897 21.747,22.495 C11.2
NetC14_2: C14.2 X1.13 | length 4.8
  Top Layer w0.178: C14.2 14.317,14.939 14.063,15.193 14.063,16.463 14.297,16.697 X1.13
NetC15_2: C15.2 X1.14 | length 1.1
  Top Layer w0.178: C15.2@16.146,14.939 X1.14@16.146,16.077
NetC19_1: C19.1 R17.2 U8.1 | length 3.4
  Top Layer w0.178: R17.2 9.047,1.349 9.534,1.836 10.059,1.836 C19.1 10.463,2.24 U8.1 ; R17.2@9.174,1.016 R17.2@9.233,1.075
NetD2_1: D2.1 R14.1 | length 2.2
  Top Layer w0.178: D2.1 13.238,3.81 13.862,4.434 R14.1 R14.1@14.507,4.451
NetD3_2: D3.2 R8.1 | length 5.9
  Top Layer w0.178: R8.1 28.483,2.133 28.965,1.651 31.886,1.651 32.661,2.426 D3.2@32.661,3.033
NetD3_3: D3.3 R10.1 | length 3.6
  Top Layer w0.178: R10.1 29.483,2.276 29.644,2.115 31.461,2.115 31.886,2.54 D3.3@31.886,3.033
NetD3_4: D3.4 R9.1 | length 2.2
  Top Layer w0.178: R9.1 31.063,2.733 31.251,2.921 31.251,3.606 31.453,3.808 D3.4@31.886,3.808
NetQ1_2: Q1.2 R3.1 | length 2.7
  Top Layer w0.178: Q1.2 24.566,2.748 24.884,2.43 R3.1
NetQ1_5: Q1.5 R6.1 | length 6.9
  Top Layer w0.178: v1(22.382,1.651) R6.1 ; Q1.5 v1(26.983,2.748)
  Bottom Layer w0.178: v1(22.382,1.651) 23.479,2.748 v1(26.983,2.748)
NetR2_1: R2.1 R16.2 U1.8 | length 4.9
  Top Layer w0.178: U1.8 16.589,6.301 17.607,5.283 R2.1 R16.2
NetR4_1: R4.1 U5.5 | length 1.5
  Top Layer w0.178: U5.5 R4.1
NetR5_2: R5.2 U1.9 | length 9.4
  Top Layer w0.178: v1(11.557,6.217) R5.2 ; U1.9 17.089,6.542 17.281,6.35 v1(17.81,6.35)
  Bottom Layer w0.178: v1(11.557,6.217) 12.635,6.217 13.264,5.588 15.625,5.588 16.387,6.35 v1(17.81,6.35)
NetR14_2: R14.2 U5.1 | length 2
  Top Layer w0.178: R14.2 16.299,4.434 16.943,3.79 U5.1
NetR15_2: R15.2 X1.12 | length 4.5
  Top Layer w0.178: X1.12 18.285,17.317 18.543,17.059 18.543,15.661 18.318,15.436 R15.2
OLED_RESET: U2.15 X1.9 | length 19
  Top Layer w0.178: v1(13.915,19.177) X1.9@16.438,19.177 ; v1(22.646,11.786) U2.15@23.604,11.786
  Bottom Layer w0.178: v1(13.915,19.177) 20.371,19.177 20.843,18.705 20.843,12.294 21.351,11.786 v1(22.646,11.786)
RED: R8.2 U2.34 | length 3
  Top Layer w0.178: R8.2 28.483,4.344 28.983,4.844 U2.34
RTS: Q1.4 R3.2 U1.24 | length 30.9
  Top Layer w0.178: U1.24 v1(18.589,13.926) v1@18.589,13.94 ; R3.2 Q1.4 ; 25.938,1.651 27.485,1.651 v1(27.774,1.94)
  Bottom Layer w0.178: v1(18.589,13.926) 18.589,14.482 17.878,15.193 16.853,15.193 15.113,13.453 15.113,10.063 18.826,6.35 18.826,4.064 19.461,3.429 27.229,3.429 27.774,2.884 v1(27.774,1.94)
RXD: U1.26 U2.40 | length 24.3
  Top Layer w0.178: v1(17.154,13.589) 17.589,13.281 U1.26 ; U2.40 31.414,8.783 v1(31.803,8.394) v1@31.803,8.592
  Bottom Layer w0.178: v1(17.154,13.589) 17.154,9.8 19.842,7.112 20.614,7.112 22.323,5.403 23.483,5.403 25.134,7.054 29.113,7.054 30.453,8.394 v1(31.803,8.394)
SCL: R13.2 TP6.1 U2.17 U6.4 U7.6 X1.10 | length 51.7
  Top Layer w0.178: v1(13.826,18.161) 14.222,18.557 X1.10 ; v1(22.382,10.44) 22.901,10.44 23.23,10.769 23.694,10.769 U2.17 ; R13.2@33.05,12.007 R13.2 ; v1(33.05,12.802) R13.2 ; U6.4 R13.2 ; U7.6 v1(37.83,9.525) 40.543,9.525 v1(42.956,7.112)
  Bottom Layer w0.178: v1(13.826,18.161) 16.816,18.161 17.324,18.669 19.99,18.669 20.244,18.415 20.244,11.852 21.682,10.414 22.356,10.414 v1(22.382,10.44) 25.314,10.44 27.676,12.802 v1(33.05,12.802) 34.041,11.811 34.287,11.811 36.573,9.525 v1(37.83,9.525)
SDA: R12.2 TP7.1 U2.20 U6.6 U7.1 X1.11 | length 39.9
  Top Layer w0.178: X1.11 v1(18.872,17.937) ; v1(22.265,8.255) 22.541,8.255 22.9,8.614 22.9,9.098 23.085,9.283 U2.20 ; U7.1@34.574,3.836 U7.1 34.68,4.725 ; U6.6 35.061,9.922 R12.2 v1(34.68,8.746) 34.68,4.725 ; v1(36.231,4.725) 34.68,4.725
  Bottom Layer w0.178: v1(18.872,17.937) 18.872,15.596 19.801,14.667 19.801,10.719 v1(22.265,8.255) ; v1@22.265,8.398 v1(22.265,8.255) ; v1@34.729,8.795 v1(34.68,8.746) 32.181,11.245 31.087,11.245 28.097,8.255 v1(22.265,8.255)
TOUCH_0: TP3.1 U2.24 | length 26.6
  Top Layer w0.178: v1(22.773,6.731) 22.773,7.081 22.975,7.283 U2.24
  Bottom Layer w0.178: v1(6.634,22.733) 12.603,16.764 16.946,16.764 19.242,14.468 19.242,10.262 v1(22.773,6.731) v1@22.773,6.744
TOUCH_1: TP8.1 U2.16 | length 28.9
  Top Layer w0.178: U2.16 23.702,11.277 23.052,11.277 22.875,11.1 22.341,11.1 21.96,11.481 21.96,12.141 22.163,12.344 22.163,13.188 22.31,13.335 23.703,13.335 23.906,13.538 23.906,19.685 26.853,22.632 31.806,22.632 33.558,24.384 36.733,24.384 v1(38.384,22.733)
TXD: U1.25 U2.41 | length 25.6
  Top Layer w0.178: v1(17.45,14.478) 17.831,14.097 17.831,13.716 18.089,13.458 U1.25 ; U2.41 v1(32.311,9.283)
  Bottom Layer w0.178: v1(17.45,14.478) 17.835,14.093 17.835,11.62 18.785,10.669 18.785,9.692 22.509,5.969 23.154,5.969 24.818,7.633 28.803,7.633 30.453,9.283 v1(32.311,9.283)
VBAT: BAT1.1 C13.1 J1.1 Q2.3 R17.1 U5.3 | length 33
  Top Layer w0.178: v1(7.374,0.889) R17.1 ; J1.1 J1.1@9.583,3.808
  Top Layer w0.305: J1.1 v1(10.571,3.836) ; Q2.3 v1(11.684,8.795) ; C13.1@14.868,1.59 v1(16.032,1.59) U5.3
  Bottom Layer w0.178: BAT1.1 BAT1.1@4.376,11.656 ; v1(7.374,0.889) 9.148,0.889 10.571,2.312 v1(10.571,3.836)
  Bottom Layer w0.305: BAT1.1@4.376,11.656 9.985,11.656 11.684,9.957 v1(11.684,8.795) 11.684,7.997 10.698,7.011 10.698,5.868 11.684,4.882 11.684,3.836 ; v1(10.571,3.836) 11.684,3.836 ; v1(16.032,1.59) 13.045,1.59 11.684,2.951 11.684,3.836
VUSB: C18.1 D1.2 D2.2 H1.1 Q2.1 R2.2 R11.1 U1.7 U3.5 U5.4 | length 47.1
  Top Layer w0.178: v1(5.07,17.287) U3.5 ; v1@14.539,6.497 v1(14.519,6.517) C18.1 15.281,7.544 15.689,7.952 U1.7 ; 18.013,4.318 19.462,4.318 19.727,4.583 R2.2 R2.2@19.541,5.097
  Top Layer w0.305: H1.1 5.307,13.873 5.897,14.463 v1(5.897,15.773) ; R11.1 D1.2 7.502,9.525 7.987,9.04 Q2.1 10.355,9.04 10.677,8.718 10.677,5.933 11.53,5.08 D2.2 13.513,5.08 14.402,5.969 15.804,5.969 17.142,4.631 17.7,4.631 18.013,4.318 18.297,4.034 18.297,1.836 18.543,1.59 U5.4 ; 14.519,5.989 v1(14.519,6.517)
  Bottom Layer w0.305: v1(5.07,17.287) 5.897,16.46 v1(5.897,15.773) 6.482,15.773 8.539,13.716 8.943,13.716 13.273,9.385 13.273,8.372 14.519,7.127 v1(14.519,6.517)
pads on no net: ANT1.3 ANT1.4 H1.4 J1. U1.1 U1.2 U1.10 U1.11 U1.12 U1.13 U1.14 U1.15 U1.16 U1.17 U1.18 U1.19 U1.20 U1.21 U1.22 U1.23 U1.27 U2.5 U2.6 U2.7 U2.8 U2.14 U2.18 U2.21 U2.22 U2.25 U2.26 U2.27 U2.28 U2.29 U2.30 U2.31 U2.32 U2.33 U2.38 U2.39 U2.42 U2.44 U2.45 U2.47 U2.48 U3.3 U3.4 U4.4 U6.2 U6.3 U6.7 U6.9 U6.13 U6.15 U6.16 U7.3 U7.4 X1.6
copper on no net:
  other v1: 6.507,2.693 7.38,2.686 8.285,2.686 6.507,5.995 7.38,5.986 8.285,5.986

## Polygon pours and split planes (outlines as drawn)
GND on Layer 1 (GND) (split plane): 227 vertices, not listed, extent 0.539,0.51 41.371,24.636
+3.3V on Layer 2 (PWR) (split plane): 208 vertices, not listed, extent 0.539,0.51 41.438,24.636

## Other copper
Top Layer:
  text "1" at 3.373,5.793 h1.02
Bottom Layer:
  text "4" at 3.103,5.793 h1.02
Layer 1 (GND) (plane layer: these items are gaps in the copper):
  pour cut-out: 39.299,5.207 cw(c39.298,5.334) 39.171,5.334 39.171,19.736 cw(c39.273,19.812) 39.273,19.939 42.422,19.939 cw(c42.422,17.272) 45.09,17.273 cw(c44.962,17.272) 45.09,17.272 45.09,7.874 cw(c42.422,7.874) 42.422,5.207 cw(c42.422,5.334) 42.421,5.207
  lines w0.254: 39.273,19.812 42.422,19.812 cw(c42.422,17.272) 44.962,17.272 44.962,7.874 cw(c42.422,7.874) 42.422,5.334 39.298,5.334 39.298,19.812
  text "2" at 3.238,5.793 h1.02
Layer 2 (PWR) (plane layer: these items are gaps in the copper):
  pour cut-out: 39.324,5.257 cw(c39.324,5.384) 39.196,5.384 39.196,19.786 cw(c39.298,19.862) 39.298,19.99 42.448,19.99 cw(c42.448,17.322) 45.115,17.323 cw(c44.988,17.322) 45.115,17.322 45.115,7.924 cw(c42.448,7.924) 42.448,5.257 cw(c42.448,5.384) 42.447,5.257
  lines w0.254: 39.298,19.812 42.448,19.812 cw(c42.448,17.272) 44.988,17.272 44.988,7.874 ; 39.324,5.334 39.324,19.812
  text "3" at 3.23,5.746 h1.02

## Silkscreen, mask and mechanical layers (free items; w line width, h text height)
Top Overlay:
  lines w0.127: 20.385,16.129 24.703,16.129
  text "ESP32 Coin" at 26.456,4.801 h0.89
  text "Rev4.0" at 26.674,0.686 h0.89
Bottom Overlay:
  drawing of 1060 lines, arcs and shapes, not listed
  text "IO35" at 39.537,22.86 h0.89
  text "IO32" at 39.664,20.417 h0.89
  text "+3.3v" at 39.4,17.806 h0.89
  text "-" at 44.962,12.192 h1.02 r90
  text "SDA" at 41.686,6.63 h0.89
  text "SCL" at 39.781,4.193 h0.89
  text "GND" at 36.573,0.94 h0.89
Mechanical 1:
  lines w0.254: 0.03,6.761 0.03,16.383 cw(c2.57,16.383) 2.111,18.881 ccw(c1.681,21.385) 4.221,21.385 4.221,22.604 cw(c6.761,22.604) 6.786,25.144 ; 0.032,6.761 ccw(c2.572,6.736) 2.572,4.196 2.902,4.196 cw(c2.902,1.656) 5.405,2.086 ccw(c7.903,2.545) 7.903,0.005 ; 6.786,25.146 38.231,25.146 ; 7.903,0 38.231,0 ; 38.231,0.002 ccw(c38.256,2.542) 40.796,2.542 40.796,2.872 cw(c43.336,2.872) 42.907,5.376 ccw(c42.448,7.874) 44.988,7.874 44.988,16.383 ccw(c42.448,16.383) 42.907,18.881 cw(c43.336,21.385) 40.796,21.385 40.796,22.604 ccw(c38.256,22.604) 38.231,25.144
